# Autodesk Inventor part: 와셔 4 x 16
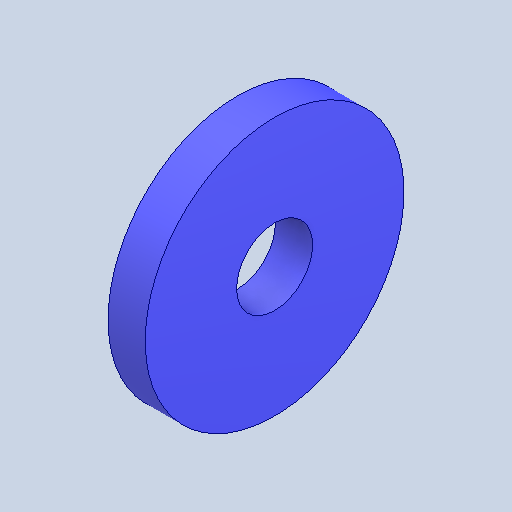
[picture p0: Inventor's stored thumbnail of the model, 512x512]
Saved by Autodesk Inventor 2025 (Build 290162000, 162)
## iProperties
Created: 2024-07
Part Number: 와셔 4 x 16
Material: 강철, 연강
Description: 미터법 평면 와셔
Document SubType Name: Modeling
Designer: SAMSUNG
Density: 7.85 g/cm^3
Appearance: 기본값
Author: jhkim
Sending System: Autodesk Inventor 2025
Preprocessor: ST-DEVELOPER v20
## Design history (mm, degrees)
feature "Solid1"
node "솔리드1"
